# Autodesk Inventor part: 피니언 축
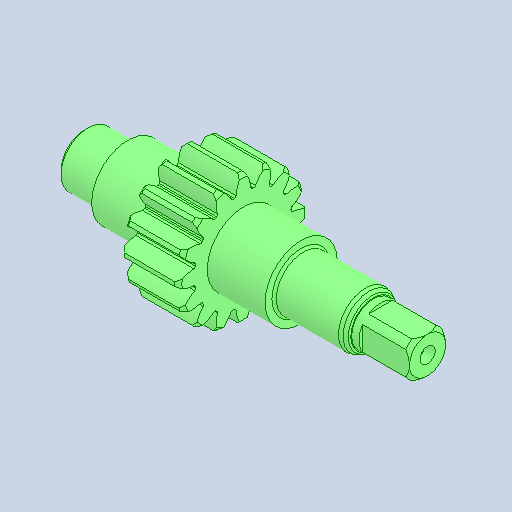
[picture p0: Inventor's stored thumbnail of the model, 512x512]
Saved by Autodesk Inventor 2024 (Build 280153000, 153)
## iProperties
Created: 2024-10
Part Number: 피니언 축
Material: 강철, 탄소
Document SubType Name: Modeling
Designer: user
Density: 7.85 g/cm^3
Appearance: 기본값
Author: jhkim
Sending System: Autodesk Inventor 2025
Preprocessor: ST-DEVELOPER v20
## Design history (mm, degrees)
feature "솔리드1"
node "솔리드2"
